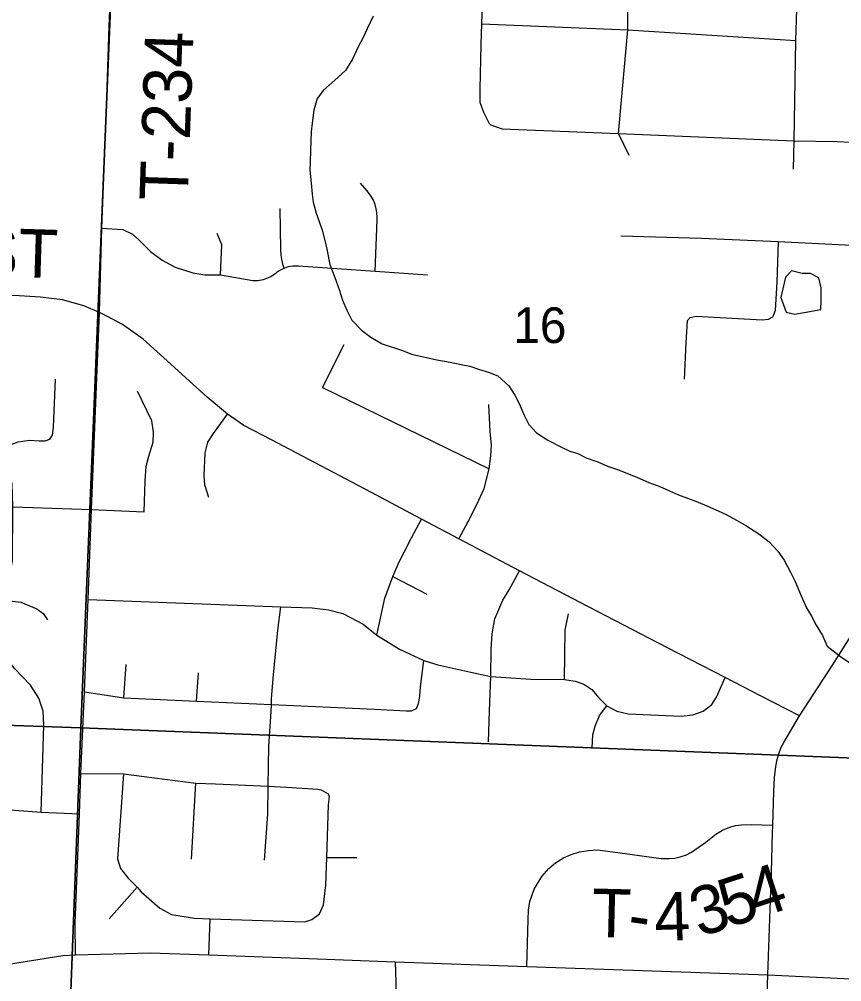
# Model space of a CAD drawing. Extents: x 0 to 34, y 0 to 22.
# Drawn here: x 5.169 to 6.135, y 17.654 to 18.784 of the extents above; entities that cross this region are included whole.
import ezdxf

# ---------------------------------------------------------------- set-up
doc = ezdxf.new("R2010")
doc.units = 0
for name, color, linetype in [('GM_X_Corporation', 7, 'Continuous'), ('GM_X_Minor_Lake', 7, 'Continuous'), ('GM_X_Minor_River', 7, 'Continuous'), ('GM_X_Section_Text', 7, 'Continuous'), ('GM_X_State_Route', 7, 'Continuous'), ('GM_X_Township_Road', 7, 'Continuous'), ('GM_X_Township_Road_Text', 7, 'Continuous')]:
    doc.layers.add(name, color=color, linetype=linetype)

msp = doc.modelspace()

# ---------------------------------------------------------------- linework, layer by layer
at = {"layer": 'GM_X_Corporation'}
for points in [[(5.2829, 18.9603), (5.2412, 17.9526), (4.2238, 17.9879), (4.2642, 18.9963)], [(5.2829, 18.9603), (6.3228, 18.9214), (6.2808, 17.9117), (5.2412, 17.9526)], [(4.2238, 17.9879), (5.2412, 17.9526), (5.2034, 16.9522), (4.1823, 16.9818)], [(5.2412, 17.9526), (6.2808, 17.9117), (6.2453, 16.9071), (5.2034, 16.9522)]]:
    msp.add_lwpolyline(points, close=True, dxfattribs=at)
at = {"layer": 'GM_X_Minor_Lake'}
for points in [[(6.1079, 18.4806), (6.098, 18.4858), (6.0881, 18.486), (6.0756, 18.4889), (6.0685, 18.4815), (6.0631, 18.4575), (6.0694, 18.4405), (6.0797, 18.438), (6.0906, 18.4401), (6.1099, 18.4434)], [(6.1099, 18.4434), (6.1104, 18.4551), (6.1104, 18.4627), (6.1103, 18.4689), (6.1079, 18.4806)]]:
    msp.add_lwpolyline(points, dxfattribs=at)
at = {"layer": 'GM_X_Minor_River'}
for points in [[(5.5844, 18.788), (5.5774, 18.7732), (5.5729, 18.7629), (5.567, 18.7518), (5.5603, 18.7376), (5.5522, 18.7243), (5.5394, 18.7127), (5.5263, 18.7012), (5.5188, 18.6912), (5.5148, 18.6775), (5.5127, 18.6623), (5.5117, 18.652)], [(5.5117, 18.652), (5.511, 18.6306), (5.5105, 18.6166), (5.5102, 18.6071), (5.5116, 18.5923), (5.5129, 18.579), (5.5142, 18.5695), (5.5177, 18.5566), (5.5209, 18.5468), (5.5248, 18.5366), (5.5277, 18.5245), (5.5301, 18.5143), (5.5337, 18.4964), (5.5393, 18.4813), (5.5444, 18.467), (5.5483, 18.4545), (5.5534, 18.4428), (5.5593, 18.4311), (5.5708, 18.4191), (5.5819, 18.4109), (5.5949, 18.4031), (5.6189, 18.3954), (5.6296, 18.391), (5.6593, 18.3846), (5.6749, 18.3818), (5.6878, 18.3789), (5.6981, 18.3772), (5.7092, 18.3731), (5.7198, 18.3699), (5.7309, 18.3655), (5.7436, 18.3539), (5.7509, 18.343), (5.756, 18.3331), (5.7615, 18.3203), (5.7673, 18.3086), (5.7762, 18.2989), (5.7896, 18.2903), (5.8048, 18.2822), (5.8152, 18.2774), (5.8247, 18.2745), (5.8346, 18.2693), (5.8483, 18.2649), (5.8598, 18.2598), (5.8712, 18.2557), (5.8842, 18.2506), (5.8949, 18.2462), (5.9082, 18.2403), (5.9212, 18.2359), (5.9323, 18.2308), (5.9429, 18.226), (5.9536, 18.2219), (5.9662, 18.2172), (5.9761, 18.2131), (5.9895, 18.2072), (5.999, 18.2028), (6.0109, 18.1961), (6.022, 18.1898), (6.0373, 18.1802), (6.0495, 18.1709), (6.0595, 18.16), (6.0669, 18.1491), (6.0747, 18.1344), (6.0801, 18.1242), (6.0868, 18.1075), (6.0931, 18.0932), (6.0993, 18.0834), (6.1047, 18.0728), (6.1121, 18.0608), (6.1176, 18.0483), (6.1333, 18.036), (6.1452, 18.0278)]]:
    msp.add_lwpolyline(points, dxfattribs=at)
at = {"layer": 'GM_X_State_Route'}
for points in [[(6.1291, 18.0348), (6.1567, 18.0779), (6.178, 18.1111), (6.2153, 18.1692), (6.2339, 18.1988), (6.2486, 18.2219), (6.2643, 18.2465), (6.2777, 18.2683), (6.2832, 18.2787), (6.2874, 18.2878), (6.2906, 18.2978), (6.293, 18.3073), (6.2946, 18.3168), (6.2961, 18.33), (6.2969, 18.3454), (6.2989, 18.3945), (6.3014, 18.4636), (6.3035, 18.5124), (6.3046, 18.5364), (6.3073, 18.5928), (6.3103, 18.6597), (6.3132, 18.7351), (6.3169, 18.8101)], [(6.0535, 17.8286), (6.0537, 17.8382), (6.0548, 17.8773), (6.0557, 17.894), (6.0573, 17.907), (6.0588, 17.9153), (6.0607, 17.9221), (6.0637, 17.9297), (6.0665, 17.9351), (6.0849, 17.9664), (6.1236, 18.0262), (6.1291, 18.0348)], [(6.048, 17.6624), (6.0503, 17.7283), (6.0521, 17.783), (6.0535, 17.8286)], [(5.9642, 17.2932), (5.9725, 17.309), (6.002, 17.3654), (6.0214, 17.4022), (6.0302, 17.4201), (6.0337, 17.428), (6.0359, 17.4342), (6.0387, 17.4443), (6.0407, 17.4542), (6.042, 17.4649), (6.0426, 17.4763), (6.0432, 17.5064), (6.0441, 17.5394), (6.048, 17.6624)], [(6.048, 17.6624), (6.203, 17.6552), (6.4083, 17.6474)]]:
    msp.add_lwpolyline(points, dxfattribs=at)
at = {"layer": 'GM_X_Township_Road'}
for p, q in [((5.5251, 18.3519), (5.5505, 18.4025)), ((5.5251, 18.3519), (5.7206, 18.2566)), ((5.1616, 18.212), (5.2537, 18.2087)), ((5.6074, 18.1301), (5.6474, 18.1094)), ((5.2919, 17.9876), (5.2944, 18.0268)), ((5.3769, 17.9838), (5.3795, 18.017)), ((5.3711, 17.7983), (5.3762, 17.8874)), ((5.53, 17.8001), (5.5655, 17.8004)), ((5.2745, 17.7283), (5.3073, 17.7652)), ((5.3916, 17.6861), (5.3933, 17.7283))]:
    msp.add_line(p, q, dxfattribs=at)
for points in [[(5.235, 17.686), (5.2348, 17.7232), (5.2396, 17.8514), (5.2414, 17.8989), (5.2456, 17.9948), (5.2499, 18.103), (5.2537, 18.2087), (5.2631, 18.4401), (5.266, 18.5391), (5.271, 18.6683), (5.2746, 18.7763), (5.2788, 18.8778), (5.2825, 18.9592), (5.2862, 19.0782), (5.29, 19.1939), (5.291, 19.2186), (5.3186, 19.9678)], [(6.0778, 18.6083), (6.0787, 18.6416), (6.0808, 18.7592), (6.0836, 18.845), (6.0865, 18.9308), (6.0877, 18.9861), (6.0908, 19.0955), (6.0909, 19.1087)], [(5.7213, 18.6607), (5.7144, 18.675), (5.7102, 18.6865), (5.7102, 18.7023), (5.7112, 18.7546), (5.712, 18.7789), (5.7147, 18.8608), (5.7174, 18.943)], [(5.885, 18.6243), (5.8725, 18.6501), (5.8835, 18.7717), (5.8827, 18.8565)], [(5.712, 18.7789), (5.8835, 18.7717), (6.0808, 18.7592)], [(5.7213, 18.6607), (5.7359, 18.6557), (5.8725, 18.6501), (6.0787, 18.6416), (6.1294, 18.6408), (6.1445, 18.64)], [(5.587, 18.4886), (5.5891, 18.549), (5.5892, 18.5521), (5.5889, 18.5571), (5.5881, 18.5618), (5.5867, 18.5669), (5.5847, 18.5718), (5.5818, 18.5771), (5.5775, 18.5828), (5.5697, 18.5918)], [(5.4799, 18.4922), (5.479, 18.4951), (5.4781, 18.4986), (5.4772, 18.5028), (5.4765, 18.5074), (5.4761, 18.5141), (5.4752, 18.562)], [(5.266, 18.5391), (5.2904, 18.5375), (5.3019, 18.5319), (5.3094, 18.5253), (5.3229, 18.5118), (5.3367, 18.5013), (5.3522, 18.4931), (5.3726, 18.4865), (5.387, 18.4842), (5.4054, 18.4842), (5.4434, 18.4776), (5.4448, 18.4775), (5.4465, 18.4775), (5.4487, 18.4776), (5.451, 18.4779), (5.4535, 18.4783), (5.4558, 18.4788), (5.4578, 18.4794), (5.4608, 18.4806), (5.4643, 18.4823), (5.4672, 18.4841), (5.4701, 18.4863), (5.4719, 18.4877), (5.4743, 18.4893), (5.4767, 18.4907), (5.4799, 18.4922), (5.4826, 18.4932), (5.4851, 18.4939), (5.4875, 18.4944), (5.49, 18.4948), (5.4933, 18.495), (5.4967, 18.4949), (5.587, 18.4886), (5.6484, 18.4843)], [(5.4054, 18.4842), (5.4068, 18.5194), (5.4012, 18.5329)], [(5.8752, 18.5299), (5.97, 18.5272), (6.0601, 18.5232), (6.1705, 18.5179), (6.3035, 18.5124)], [(6.0601, 18.5232), (6.0583, 18.4755), (6.0564, 18.4422), (6.0536, 18.4349)], [(5.2718, 18.4356), (5.2631, 18.4401), (5.2447, 18.4477), (5.2197, 18.4549), (5.194, 18.4582), (5.169, 18.4595), (4.9315, 18.4661), (4.8719, 18.4684), (4.6236, 18.4752), (4.4743, 18.4812), (4.3338, 18.4879), (4.2439, 18.4919), (4.1405, 18.4961), (4.0385, 18.501), (3.8897, 18.5061), (3.7543, 18.5105)], [(6.0849, 17.9664), (6.0393, 17.9901), (5.9976, 18.0114), (5.93, 18.0462), (5.8274, 18.0994), (5.7563, 18.1366), (5.685, 18.1742), (5.6413, 18.1973), (5.5817, 18.2293), (5.465, 18.2904), (5.4327, 18.3073), (5.4133, 18.3205), (5.3897, 18.3405), (5.3647, 18.3635), (5.3426, 18.3833), (5.3144, 18.4089), (5.29, 18.426), (5.2718, 18.4356)], [(5.9502, 18.3617), (5.9519, 18.4043), (5.9536, 18.4308), (5.9566, 18.4343)], [(5.9566, 18.4343), (5.9637, 18.4356), (6.0412, 18.4315), (6.0485, 18.4324), (6.0536, 18.4349)], [(5.143, 18.2708), (5.1519, 18.28), (5.1575, 18.2843), (5.1677, 18.2882), (5.1809, 18.2902), (5.1924, 18.2895), (5.1993, 18.2895), (5.2049, 18.2915), (5.2082, 18.2961), (5.2091, 18.305), (5.2114, 18.3619)], [(5.2537, 18.2087), (5.3156, 18.2061), (5.3167, 18.2426), (5.3178, 18.2597), (5.3211, 18.2713), (5.3261, 18.2878), (5.3267, 18.2994), (5.3245, 18.3127), (5.3079, 18.3475)], [(5.685, 18.1742), (5.6961, 18.1945), (5.7067, 18.2153), (5.715, 18.2333), (5.7206, 18.2566), (5.7228, 18.2718), (5.7235, 18.2843), (5.7218, 18.3002), (5.7203, 18.332)], [(5.3916, 18.2228), (5.387, 18.2379), (5.386, 18.2488), (5.3874, 18.2754), (5.3903, 18.2879), (5.3969, 18.2981), (5.4133, 18.3205)], [(5.1948, 17.8534), (5.198, 17.9556), (5.197, 17.9721), (5.192, 17.9872), (5.1822, 18.0027), (5.1638, 18.0217), (5.1516, 18.0375), (5.1493, 18.0454), (5.1457, 18.0632), (5.148, 18.101), (5.1491, 18.1133), (5.1508, 18.1205), (5.1588, 18.1367), (5.1611, 18.148), (5.1616, 18.212), (5.1608, 18.2389), (5.1549, 18.2563), (5.143, 18.2708), (5.1286, 18.2771), (5.1167, 18.279), (5.0704, 18.281), (4.9997, 18.2823)], [(4.949, 18.2081), (4.9546, 18.1958), (4.9933, 18.1272), (5.0026, 18.1163), (5.0161, 18.109), (5.0267, 18.1057), (5.0375, 18.1051), (5.073, 18.1041), (5.148, 18.101), (5.161, 18.101), (5.1709, 18.0999), (5.1897, 18.0921), (5.1971, 18.0865), (5.2022, 18.0791)], [(5.5887, 18.0614), (5.5982, 18.1046), (5.6074, 18.1301), (5.6152, 18.1472), (5.621, 18.1588), (5.6294, 18.1756), (5.6413, 18.1973)], [(5.7198, 17.936), (5.721, 17.9725), (5.7226, 18.0128), (5.723, 18.0447), (5.7241, 18.0628), (5.7275, 18.0805), (5.7369, 18.1025), (5.7441, 18.1146), (5.7563, 18.1366)], [(5.2499, 18.103), (5.4761, 18.0946), (5.513, 18.0932), (5.532, 18.0911), (5.5488, 18.0868), (5.5729, 18.074), (5.5887, 18.0614), (5.6156, 18.0449), (5.6441, 18.0314), (5.6604, 18.0263), (5.6992, 18.0176), (5.7226, 18.0128), (5.7696, 18.0097), (5.8091, 18.009), (5.8218, 18.0072), (5.8317, 18.0037), (5.8411, 17.9974), (5.8496, 17.9875), (5.859, 17.9783), (5.8707, 17.972), (5.8837, 17.9689), (5.9461, 17.966), (5.9599, 17.9676), (5.9721, 17.972), (5.9821, 17.9797), (5.9876, 17.9883), (5.9976, 18.0114)], [(5.457, 17.7969), (5.4607, 17.8509), (5.4613, 17.8838), (5.462, 17.9311), (5.4647, 17.9718), (5.465, 17.9798), (5.4653, 17.9867), (5.4673, 18.0148), (5.4726, 18.0671), (5.4761, 18.0946)], [(5.8091, 18.009), (5.8101, 18.067), (5.8139, 18.0864)], [(5.2456, 17.9948), (5.2919, 17.9876), (5.3769, 17.9838), (5.465, 17.9798), (5.586, 17.9744), (5.6232, 17.9723), (5.6296, 17.9725), (5.6352, 17.975), (5.6376, 17.9812), (5.6392, 17.9892), (5.6399, 18.0006), (5.6441, 18.0314)], [(5.8415, 17.929), (5.8425, 17.9442), (5.8451, 17.9544), (5.8503, 17.967), (5.859, 17.9783)], [(4.9265, 17.9006), (4.9372, 17.9004), (4.9481, 17.8978), (4.9694, 17.8868), (4.9813, 17.8879), (4.9881, 17.8894), (5.0001, 17.8894), (5.0115, 17.8877), (5.0285, 17.8777), (5.0404, 17.8699), (5.0507, 17.8662), (5.0694, 17.8615), (5.1084, 17.8591), (5.1265, 17.8586), (5.1948, 17.8534), (5.2396, 17.8514)], [(5.2414, 17.8989), (5.2915, 17.8983), (5.3762, 17.8874), (5.3993, 17.8867), (5.4613, 17.8838), (5.4827, 17.8829), (5.5194, 17.8804), (5.5236, 17.8798), (5.524, 17.8791)], [(5.2915, 17.8983), (5.2845, 17.7986), (5.2879, 17.7873), (5.297, 17.7758), (5.3073, 17.7652), (5.3123, 17.7601), (5.3342, 17.7407), (5.3477, 17.7333), (5.3747, 17.7289), (5.3933, 17.7283), (5.5043, 17.7245), (5.5125, 17.7275), (5.5213, 17.7339), (5.5262, 17.7447), (5.5288, 17.7676), (5.53, 17.8001), (5.5322, 17.8619), (5.5334, 17.8714), (5.5321, 17.8744), (5.524, 17.8791)], [(5.7651, 17.6722), (5.7666, 17.7273), (5.767, 17.7383), (5.7686, 17.7485), (5.7735, 17.7629), (5.7826, 17.778), (5.7909, 17.7874), (5.7987, 17.7939), (5.8078, 17.7997), (5.8168, 17.8037), (5.8267, 17.8069), (5.8373, 17.8086), (5.8477, 17.8091), (5.8716, 17.8059), (5.9001, 17.8023), (5.9141, 17.8003), (5.9228, 17.7992), (5.9322, 17.7989), (5.9386, 17.7995), (5.9451, 17.8008), (5.9525, 17.8032), (5.9584, 17.8064), (5.9749, 17.8182), (5.9869, 17.8275), (5.9946, 17.8324), (6.0032, 17.8359), (6.01, 17.8378), (6.0168, 17.8386), (6.0285, 17.8388), (6.0537, 17.8382)], [(5.1463, 17.6733), (5.2202, 17.685), (5.235, 17.686), (5.3232, 17.6883), (5.3916, 17.6861), (5.5192, 17.6811)], [(5.5192, 17.6811), (5.6104, 17.6776), (5.7651, 17.6722), (6.048, 17.6624)], [(5.6104, 17.6776), (5.6112, 17.6534), (5.6108, 17.6346), (5.6091, 17.6276), (5.6056, 17.6192), (5.6007, 17.612), (5.5967, 17.6083)]]:
    msp.add_lwpolyline(points, dxfattribs=at)

# ---------------------------------------------------------------- texts
at = {"layer": 'GM_X_Section_Text'}
msp.add_text('16', height=0.04186, rotation=0, dxfattribs=at).set_placement((5.7491, 18.4042))
at = {"layer": 'GM_X_Township_Road_Text'}
for s, height, rotation, p in [('T-234', 0.05682, 88.0355, (5.3668, 18.5706)), ('ST', 0.05682, 358.2167, (5.1165, 18.4832)), ('4', 0.0568, 18.1487, (6.0343, 17.728)), ('5', 0.0568, 17.9988, (6.0009, 17.7172)), ('T', 0.0568, 358.5727, (5.8406, 17.7071)), ('3', 0.0568, 18.1668, (5.9677, 17.7063)), ('4', 0.0568, 1.6719, (5.9152, 17.7022)), ('-', 0.0568, 351.5862, (5.8812, 17.7062))]:
    msp.add_text(s, height=height, rotation=rotation, dxfattribs=at).set_placement(p)

doc.saveas('drawing.dxf')
